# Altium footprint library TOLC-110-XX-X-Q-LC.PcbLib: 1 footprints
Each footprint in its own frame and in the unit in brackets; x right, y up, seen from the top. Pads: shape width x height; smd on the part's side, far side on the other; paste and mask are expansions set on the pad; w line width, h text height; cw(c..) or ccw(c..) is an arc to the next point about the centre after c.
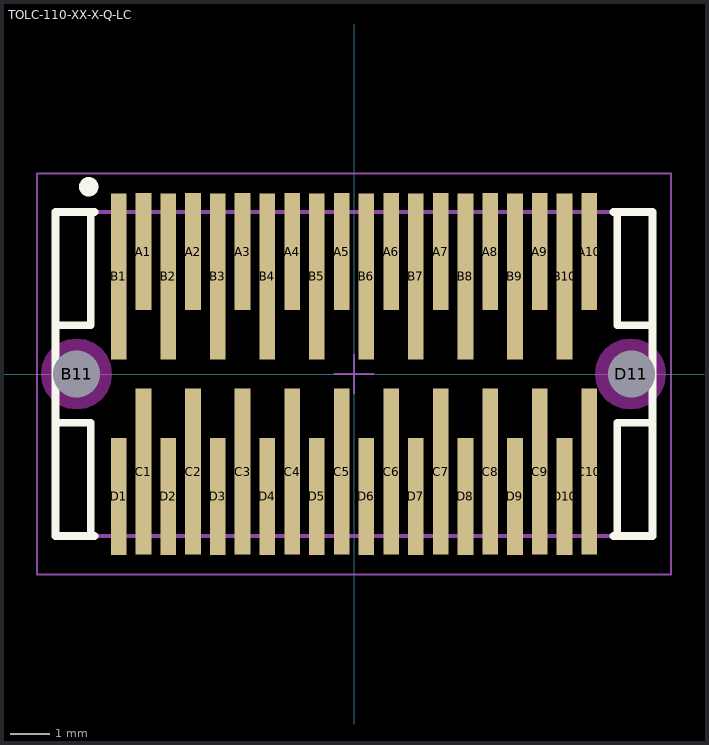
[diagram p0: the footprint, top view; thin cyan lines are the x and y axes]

## TOLC-110-XX-X-Q-LC [mm] "1.27mm pitch, 40 pin, terminal strip; 4 rows, w/locking clips, SMT"
height 5.59
pads (42):
  rect 0.4x3 smd mask+0: A1(-5.397,3.135) A2(-4.127,3.135) A3(-2.857,3.135) A4(-1.587,3.135) A5(-0.318,3.135) A6(0.953,3.135) A7(2.222,3.135) A8(3.492,3.135) A9(4.763,3.135) A10(6.032,3.135) D1(-6.032,-3.135) D2(-4.763,-3.135) D3(-3.492,-3.135) D4(-2.222,-3.135) D5(-0.953,-3.135) D6(0.318,-3.135) D7(1.587,-3.135) D8(2.857,-3.135) D9(4.127,-3.135) D10(5.397,-3.135)
  rect 0.4x4.25 smd mask+0: B1(-6.032,2.5) B2(-4.763,2.5) B3(-3.492,2.5) B4(-2.222,2.5) B5(-0.953,2.5) B6(0.318,2.5) B7(1.587,2.5) B8(2.857,2.5) B9(4.127,2.5) B10(5.397,2.5) C1(-5.397,-2.5) C2(-4.127,-2.5) C3(-2.857,-2.5) C4(-1.587,-2.5) C5(-0.318,-2.5) C6(0.953,-2.5) C7(2.222,-2.5) C8(3.492,-2.5) C9(4.763,-2.5) C10(6.032,-2.5)
  round 1 hole 1.2 unplated mask+0: B11(-7.112,0) D11(7.112,0)
Top Overlay:
  circle w0.25: c-6.8,4.8 r0.125
  lines w0.2: -7.65,-1.25 -6.75,-1.25 -6.75,-4.15 ; -7.65,1.25 -6.75,1.25 -6.75,4.15 ; -6.65,-4.15 -7.65,-4.15 -7.65,4.15 -6.65,4.15 ; 6.65,-4.15 7.65,-4.15 7.65,4.15 6.65,4.15 ; 6.75,-4.15 6.75,-1.25 7.65,-1.25 ; 6.75,4.15 6.75,1.25 7.65,1.25
Keep-Out Layer:
  pour cut-out: 7.995,0 7.964,0.235 7.873,0.454 7.729,0.642 7.541,0.786 7.322,0.877 7.087,0.908 6.852,0.877 6.633,0.786 6.445,0.642 6.301,0.454 6.21,0.235 6.179,0 6.21,-0.235 6.301,-0.454 6.445,-0.642 6.633,-0.786 6.852,-0.877 7.087,-0.908 7.322,-0.877 7.541,-0.786 7.729,-0.642 7.873,-0.454 7.964,-0.235
  pour cut-out: -6.205,0 -6.236,0.235 -6.327,0.454 -6.471,0.642 -6.659,0.786 -6.878,0.877 -7.113,0.908 -7.348,0.877 -7.567,0.786 -7.755,0.642 -7.899,0.454 -7.99,0.235 -8.021,0 -7.99,-0.235 -7.899,-0.454 -7.755,-0.642 -7.567,-0.786 -7.348,-0.877 -7.113,-0.908 -6.878,-0.877 -6.659,-0.786 -6.471,-0.642 -6.327,-0.454 -6.236,-0.235
Mechanical 12:
  lines w0.001: -7.65,-4.15 -7.65,4.15 7.65,4.15 7.65,-4.15 -7.65,-4.15 ; -7.65,-1.25 -6.75,-1.25 -6.75,-4.15 6.75,-4.15 6.75,-1.25 7.65,-1.25 7.65,1.25 6.75,1.25 6.75,4.15 -6.75,4.15 -6.75,1.25 -7.65,1.25 -7.65,-1.25
Mechanical 13:
  circle w0.1: c-6.054,3.349 r0.127
  lines w0.1: -7.65,-4.15 -7.65,4.15 7.65,4.15 7.65,-4.15 -7.65,-4.15 ; -7.65,-1.25 -6.75,-1.25 -6.75,-4.15 6.75,-4.15 6.75,-1.25 7.65,-1.25 7.65,1.25 6.75,1.25 6.75,4.15 -6.75,4.15 -6.75,1.25 -7.65,1.25 -7.65,-1.25
  text ".Designator" at 0,-0.127 h1.52
Mechanical 15:
  lines w0.05: -0.5,0 0.5,0 ; 0,-0.5 0,0.5 ; -8.128,-5.143 8.128,-5.143 8.128,5.143 -8.128,5.143 -8.128,-5.143
Mechanical 16:
  circle w0.001: c-6.054,3.349 r0.127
